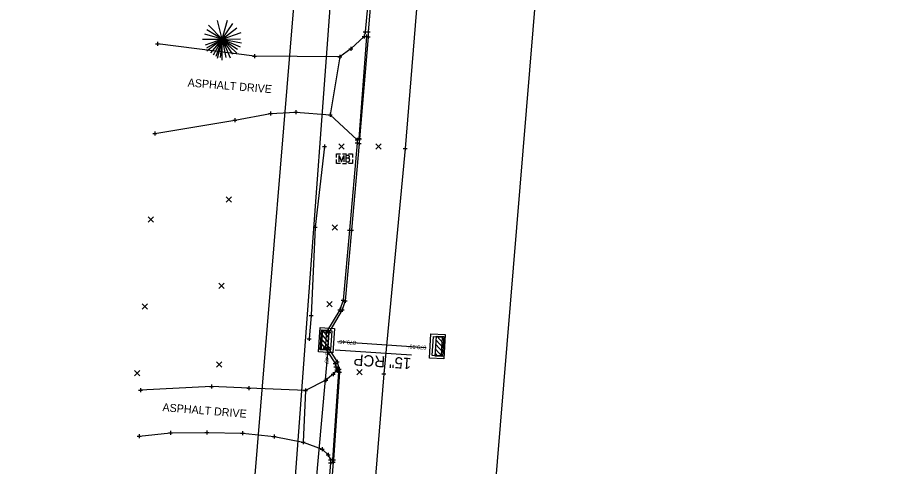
# Model space of a CAD drawing. Extents: x 1380550 to 1381945, y 468927 to 470496.
# Drawn here: x 1381450.4 to 1381668.9, y 469266.4 to 469378.6 of the extents above; entities that cross this region are included whole.
import ezdxf

# ---------------------------------------------------------------- set-up
doc = ezdxf.new("R2010")
doc.units = 0
for name, color, linetype in [('DR_X_Cells', 7, 'Continuous'), ('DR_X_Ditch', 7, 'Continuous'), ('DR_X_Storm_Sewer', 7, 'Continuous'), ('DR_X_Text', 7, 'Continuous'), ('GK_Drainage_Nodes', 7, 'Continuous'), ('PV_X_COP', 7, 'Continuous'), ('PV_X_Curb', 7, 'Continuous'), ('PV_X_Driveway', 7, 'Continuous'), ('PV_X_EOP', 7, 'Continuous'), ('RD_X_Cells', 7, 'Continuous'), ('RD_X_Text', 7, 'Continuous'), ('RW_X_Esmt_General', 7, 'Continuous'), ('SC_Scratch1', 7, 'Continuous'), ('SV_X_Random_Point', 7, 'Continuous'), ('SV_X_Shot_Marker', 7, 'Continuous'), ('UT_X_Electric', 7, 'Continuous'), ('UT_X_Telecom', 7, 'Continuous'), ('VG_X_Cells', 7, 'Continuous')]:
    doc.layers.add(name, color=color, linetype=linetype)

msp = doc.modelspace()

# ---------------------------------------------------------------- linework, layer by layer
at = {"layer": 'DR_X_Cells'}
for p, q in [((1381526.46, 469300.57), (1381528.09, 469298.69)), ((1381527.59, 469300.49), (1381528.17, 469299.82)), ((1381526.23, 469298.39), (1381527.93, 469296.44)), ((1381526.31, 469299.52), (1381528.01, 469297.56)), ((1381556.79, 469296.04), (1381555.06, 469297.97)), ((1381556.85, 469297.17), (1381555.25, 469298.95)), ((1381556.91, 469298.3), (1381556.39, 469298.89)), ((1381526.07, 469296.14), (1381526.58, 469295.54)), ((1381526.15, 469297.26), (1381527.71, 469295.46)), ((1381556.59, 469293.87), (1381554.93, 469295.72)), ((1381556.72, 469294.92), (1381554.99, 469296.84)), ((1381555.46, 469293.93), (1381554.87, 469294.59))]:
    msp.add_line(p, q, dxfattribs=at)
for points in [[(1381529.67, 469300.88), (1381529.23, 469294.81), (1381525.66, 469295.07), (1381526.09, 469301.14)], [(1381528.22, 469300.44), (1381527.86, 469295.45), (1381526.03, 469295.58), (1381526.39, 469300.57)], [(1381528.96, 469300.26), (1381528.62, 469295.52), (1381526.37, 469295.69), (1381526.71, 469300.42)], [(1381553.39, 469293.5), (1381553.73, 469299.58), (1381557.3, 469299.38), (1381556.97, 469293.3)], [(1381554.09, 469294.13), (1381554.36, 469298.87), (1381556.6, 469298.75), (1381556.34, 469294.01)], [(1381554.84, 469293.96), (1381555.11, 469298.96), (1381556.94, 469298.85), (1381556.67, 469293.86)]]:
    msp.add_lwpolyline(points, close=True, dxfattribs=at)
at = {"layer": 'DR_X_Ditch'}
msp.add_lwpolyline([(1381527.14, 469346.36), (1381524.79, 469326.2), (1381523.85, 469304.1), (1381523.31, 469298.29)], dxfattribs=at)
at = {"layer": 'DR_X_Storm_Sewer'}
for p, q in [((1381528.04, 469296.45), (1381500.71, 468992.41)), ((1381552.6, 469296.08), (1381530.41, 469297.57))]:
    msp.add_line(p, q, dxfattribs=at)
at = {"layer": 'DR_X_Text'}
msp.add_line((1381529.85, 469295.58), (1381548.9, 469294.3), dxfattribs=at)
at = {"layer": 'GK_Drainage_Nodes'}
for p, q in [((1381527.83, 469300.34), (1381527.83, 469300.34)), ((1381525.88, 469298.1), (1381525.88, 469298.1)), ((1381526.54, 469298.05), (1381526.54, 469298.05)), ((1381527.66, 469297.97), (1381527.66, 469297.97)), ((1381528.04, 469297.95), (1381528.04, 469297.95)), ((1381528.04, 469297.95), (1381528.04, 469297.95)), ((1381528.79, 469297.89), (1381528.79, 469297.89)), ((1381529.45, 469297.85), (1381529.45, 469297.85)), ((1381555.48, 469298.81), (1381555.48, 469298.81)), ((1381527.49, 469295.6), (1381527.49, 469295.6)), ((1381553.56, 469296.54), (1381553.56, 469296.54)), ((1381554.22, 469296.5), (1381554.22, 469296.5)), ((1381554.97, 469296.46), (1381554.97, 469296.46)), ((1381554.97, 469296.46), (1381554.97, 469296.46)), ((1381555.35, 469296.44), (1381555.35, 469296.44)), ((1381556.47, 469296.38), (1381556.47, 469296.38)), ((1381557.14, 469296.34), (1381557.14, 469296.34)), ((1381555.22, 469294.07), (1381555.22, 469294.07))]:
    msp.add_line(p, q, dxfattribs=at)
at = {"layer": 'PV_X_COP'}
msp.add_lwpolyline([(1381585.99, 469815.58), (1381581.29, 469760.78), (1381580.3, 469747.86), (1381578.72, 469729.45), (1381576.78, 469708.95), (1381575.29, 469689.79), (1381572.76, 469657.56), (1381569.36, 469615.7), (1381565.36, 469567.23), (1381561.16, 469537.52), (1381558.94, 469486.81), (1381555.39, 469442.03), (1381550.97, 469391.02), (1381547.28, 469345.9), (1381541.95, 469289.55), (1381537.19, 469231.27), (1381533.05, 469168.09), (1381530.32, 469133.74), (1381523.97, 469065.08), (1381520.12, 469021.37), (1381518.18, 469001.31)], dxfattribs=at)
at = {"layer": 'PV_X_Curb'}
for points in [[(1381538.96, 469393.9), (1381538.97, 469392.95), (1381537.34, 469375.04), (1381537.07, 469373.85)], [(1381535.34, 469347.99), (1381535.28, 469347.29), (1381533.36, 469325.49), (1381531.78, 469307.95), (1381530.98, 469305.57), (1381527.65, 469300.02), (1381527.35, 469296.02), (1381529.77, 469292.16), (1381529.97, 469291.26), (1381530.24, 469290.52)], [(1381528.62, 469268.06), (1381528.68, 469267.34), (1381525.83, 469232.26), (1381523.03, 469197.27), (1381522.81, 469196)]]:
    msp.add_lwpolyline(points, dxfattribs=at)
at = {"layer": 'PV_X_Driveway'}
for points in [[(1381537.07, 469373.85), (1381533.72, 469370.74), (1381530.94, 469368.81), (1381528.58, 469354.27), (1381535.34, 469347.99)], [(1381537.07, 469373.85), (1381537.66, 469373.84), (1381535.7, 469348.38), (1381535.34, 469347.99)], [(1381530.94, 469368.81), (1381509.64, 469368.9), (1381485.43, 469371.98)], [(1381484.73, 469349.64), (1381504.73, 469352.92), (1381513.61, 469354.59), (1381519.99, 469354.96), (1381528.58, 469354.27)], [(1381530.24, 469290.52), (1381529.29, 469289.43), (1381527.48, 469288), (1381522.43, 469285.41), (1381521.8, 469272.45), (1381526.53, 469270.72), (1381528.04, 469269.3), (1381528.62, 469268.06)], [(1381530.24, 469290.52), (1381530.57, 469290.63), (1381530.67, 469290.02), (1381529.16, 469268.09), (1381528.62, 469268.06)], [(1381522.43, 469285.41), (1381508.26, 469285.98), (1381498.91, 469286.38), (1381481.14, 469285.44)], [(1381480.8, 469273.97), (1381488.65, 469274.82), (1381497.76, 469274.89), (1381506.68, 469274.7), (1381514.52, 469273.9), (1381521.8, 469272.45)]]:
    msp.add_lwpolyline(points, dxfattribs=at)
at = {"layer": 'PV_X_EOP'}
msp.add_line((1381533.72, 469370.74), (1381533.72, 469370.74), dxfattribs=at)
msp.add_lwpolyline([(1381539.58, 469392.93), (1381538.09, 469374.98), (1381538.03, 469373.76), (1381535.92, 469348.28), (1381535.79, 469347.09), (1381533.91, 469325.42), (1381532.32, 469307.8), (1381531.56, 469305.55), (1381528.19, 469299.9), (1381527.99, 469296.13), (1381530.34, 469292.53), (1381530.8, 469290.75), (1381530.92, 469290), (1381529.4, 469268.09), (1381529.3, 469267.44), (1381526.47, 469232.31), (1381523.61, 469197.35), (1381523.61, 469196.13), (1381521.19, 469168.77), (1381520.16, 469156.66)], dxfattribs=at)
at = {"layer": 'RD_X_Cells'}
for p, q in [((1381531.63, 469344.56), (1381532.63, 469344.56)), ((1381531.63, 469342.12), (1381532.63, 469342.12)), ((1381532.14, 469343.34), (1381532.14, 469343.34))]:
    msp.add_line(p, q, dxfattribs=at)
for points in [[(1381530.14, 469343.59), (1381530.14, 469344.56), (1381531.11, 469344.56)], [(1381530.85, 469342.54), (1381530.85, 469344.14), (1381531.43, 469342.54), (1381531.98, 469344.14), (1381531.98, 469342.54)], [(1381533.16, 469343.41), (1381533.23, 469343.47), (1381533.26, 469343.51), (1381533.29, 469343.55), (1381533.3, 469343.57), (1381533.33, 469343.62), (1381533.34, 469343.66), (1381533.37, 469343.75), (1381533.37, 469343.79), (1381533.37, 469343.84), (1381533.35, 469343.91), (1381533.33, 469343.98), (1381533.29, 469344.03), (1381533.23, 469344.08), (1381533.18, 469344.1), (1381533.15, 469344.11), (1381533.09, 469344.14), (1381532.47, 469344.14), (1381532.47, 469342.54), (1381533.16, 469342.54), (1381533.25, 469342.59), (1381533.33, 469342.65), (1381533.39, 469342.75), (1381533.43, 469342.87), (1381533.44, 469342.98), (1381533.44, 469343.06), (1381533.42, 469343.13), (1381533.37, 469343.25), (1381533.3, 469343.32), (1381533.16, 469343.41), (1381532.47, 469343.41)], [(1381533.15, 469344.56), (1381534.14, 469344.56), (1381534.14, 469343.59)], [(1381531.11, 469342.12), (1381530.14, 469342.12), (1381530.14, 469343.09)], [(1381534.14, 469343.09), (1381534.14, 469342.12), (1381533.15, 469342.12)]]:
    msp.add_lwpolyline(points, dxfattribs=at)
at = {"layer": 'RW_X_Esmt_General'}
for points in [[(1381490.4, 469029.46), (1381590.2, 470237.18), (1380558.69, 470277.03)], [(1381783.19, 470213.89), (1381648.78, 470217.49), (1381563.79, 469189.03)]]:
    msp.add_lwpolyline(points, dxfattribs=at)
at = {"layer": 'SV_X_Random_Point'}
for p, q in [((1381530.69, 469345.66), (1381532.03, 469347)), ((1381530.69, 469347), (1381532.03, 469345.66)), ((1381539.96, 469345.66), (1381541.3, 469346.99)), ((1381539.96, 469346.99), (1381541.3, 469345.66)), ((1381502.57, 469332.47), (1381503.9, 469333.8)), ((1381502.57, 469333.8), (1381503.9, 469332.47)), ((1381483.09, 469327.43), (1381484.43, 469328.77)), ((1381483.09, 469328.77), (1381484.43, 469327.43)), ((1381529.05, 469325.46), (1381530.39, 469326.8)), ((1381529.05, 469326.8), (1381530.39, 469325.46)), ((1381500.73, 469310.9), (1381502.06, 469312.23)), ((1381500.73, 469312.23), (1381502.06, 469310.9)), ((1381481.56, 469305.72), (1381482.89, 469307.06)), ((1381481.56, 469307.06), (1381482.89, 469305.72)), ((1381527.74, 469306.31), (1381529.07, 469307.65)), ((1381527.74, 469307.65), (1381529.07, 469306.31)), ((1381500.16, 469291.24), (1381501.49, 469292.58)), ((1381500.16, 469292.58), (1381501.49, 469291.24)), ((1381479.67, 469289.03), (1381481, 469290.37)), ((1381479.67, 469290.37), (1381481, 469289.03)), ((1381535.2, 469289.33), (1381536.53, 469290.66)), ((1381535.2, 469290.66), (1381536.53, 469289.33))]:
    msp.add_line(p, q, dxfattribs=at)
at = {"layer": 'SV_X_Shot_Marker'}
for p, q in [((1381536.84, 469375.04), (1381537.84, 469375.04)), ((1381537.07, 469374.35), (1381537.07, 469373.35)), ((1381537.07, 469374.35), (1381537.07, 469373.35)), ((1381537.07, 469374.35), (1381537.07, 469373.35)), ((1381537.34, 469375.54), (1381537.34, 469374.54)), ((1381537.34, 469375.04), (1381537.34, 469375.04)), ((1381537.59, 469374.98), (1381538.59, 469374.98)), ((1381537.66, 469374.34), (1381537.66, 469373.34)), ((1381538.03, 469374.26), (1381538.03, 469373.26)), ((1381538.09, 469375.48), (1381538.09, 469374.48)), ((1381538.09, 469374.98), (1381538.09, 469374.98)), ((1381485.43, 469372.48), (1381485.43, 469371.48)), ((1381536.57, 469373.85), (1381537.57, 469373.85)), ((1381536.57, 469373.85), (1381537.57, 469373.85)), ((1381536.57, 469373.85), (1381537.57, 469373.85)), ((1381537.07, 469373.85), (1381537.07, 469373.85)), ((1381537.07, 469373.85), (1381537.07, 469373.85)), ((1381537.07, 469373.85), (1381537.07, 469373.85)), ((1381537.16, 469373.84), (1381538.16, 469373.84)), ((1381537.53, 469373.76), (1381538.53, 469373.76)), ((1381537.66, 469373.84), (1381537.66, 469373.84)), ((1381538.03, 469373.76), (1381538.03, 469373.76)), ((1381484.93, 469371.98), (1381485.93, 469371.98)), ((1381485.43, 469371.98), (1381485.43, 469371.98)), ((1381533.22, 469370.74), (1381534.22, 469370.74)), ((1381533.22, 469370.74), (1381534.22, 469370.74)), ((1381533.72, 469371.24), (1381533.72, 469370.24)), ((1381533.72, 469371.24), (1381533.72, 469370.24)), ((1381533.72, 469370.74), (1381533.72, 469370.74)), ((1381533.72, 469370.74), (1381533.72, 469370.74)), ((1381509.14, 469368.9), (1381510.14, 469368.9)), ((1381509.64, 469369.4), (1381509.64, 469368.4)), ((1381509.64, 469368.9), (1381509.64, 469368.9)), ((1381530.44, 469368.81), (1381531.44, 469368.81)), ((1381530.44, 469368.81), (1381531.44, 469368.81)), ((1381530.94, 469369.31), (1381530.94, 469368.31)), ((1381530.94, 469369.31), (1381530.94, 469368.31)), ((1381530.94, 469368.81), (1381530.94, 469368.81)), ((1381530.94, 469368.81), (1381530.94, 469368.81)), ((1381513.11, 469354.59), (1381514.11, 469354.59)), ((1381513.61, 469355.09), (1381513.61, 469354.09)), ((1381513.61, 469354.59), (1381513.61, 469354.59)), ((1381519.49, 469354.96), (1381520.49, 469354.96)), ((1381519.99, 469355.46), (1381519.99, 469354.46)), ((1381519.99, 469354.96), (1381519.99, 469354.96)), ((1381528.58, 469354.77), (1381528.58, 469353.77)), ((1381528.58, 469354.77), (1381528.58, 469353.77)), ((1381504.23, 469352.92), (1381505.23, 469352.92)), ((1381504.73, 469353.42), (1381504.73, 469352.42)), ((1381504.73, 469352.92), (1381504.73, 469352.92)), ((1381528.08, 469354.27), (1381529.08, 469354.27)), ((1381528.08, 469354.27), (1381529.08, 469354.27)), ((1381528.58, 469354.27), (1381528.58, 469354.27)), ((1381528.58, 469354.27), (1381528.58, 469354.27)), ((1381484.23, 469349.64), (1381485.23, 469349.64)), ((1381484.73, 469350.14), (1381484.73, 469349.14)), ((1381484.73, 469349.64), (1381484.73, 469349.64)), ((1381535.2, 469348.38), (1381536.2, 469348.38)), ((1381535.34, 469348.49), (1381535.34, 469347.49)), ((1381535.34, 469348.49), (1381535.34, 469347.49)), ((1381535.34, 469348.49), (1381535.34, 469347.49)), ((1381535.42, 469348.28), (1381536.42, 469348.28)), ((1381535.7, 469348.88), (1381535.7, 469347.88)), ((1381535.7, 469348.38), (1381535.7, 469348.38)), ((1381535.92, 469348.78), (1381535.92, 469347.78)), ((1381535.92, 469348.28), (1381535.92, 469348.28)), ((1381526.64, 469346.36), (1381527.64, 469346.36)), ((1381527.14, 469346.86), (1381527.14, 469345.86)), ((1381527.14, 469346.36), (1381527.14, 469346.36)), ((1381534.78, 469347.29), (1381535.78, 469347.29)), ((1381534.84, 469347.99), (1381535.84, 469347.99)), ((1381534.84, 469347.99), (1381535.84, 469347.99)), ((1381534.84, 469347.99), (1381535.84, 469347.99)), ((1381535.28, 469347.79), (1381535.28, 469346.79)), ((1381535.28, 469347.29), (1381535.28, 469347.29)), ((1381535.29, 469347.09), (1381536.29, 469347.09)), ((1381535.34, 469347.99), (1381535.34, 469347.99)), ((1381535.34, 469347.99), (1381535.34, 469347.99)), ((1381535.34, 469347.99), (1381535.34, 469347.99)), ((1381535.79, 469347.59), (1381535.79, 469346.59)), ((1381535.79, 469347.09), (1381535.79, 469347.09)), ((1381546.78, 469345.9), (1381547.78, 469345.9)), ((1381547.28, 469346.4), (1381547.28, 469345.4)), ((1381547.28, 469345.9), (1381547.28, 469345.9)), ((1381524.29, 469326.2), (1381525.29, 469326.2)), ((1381524.79, 469326.7), (1381524.79, 469325.7)), ((1381524.79, 469326.2), (1381524.79, 469326.2)), ((1381532.86, 469325.49), (1381533.86, 469325.49)), ((1381533.36, 469325.99), (1381533.36, 469324.99)), ((1381533.36, 469325.49), (1381533.36, 469325.49)), ((1381533.41, 469325.42), (1381534.41, 469325.42)), ((1381533.91, 469325.92), (1381533.91, 469324.92)), ((1381533.91, 469325.42), (1381533.91, 469325.42)), ((1381531.28, 469307.95), (1381532.28, 469307.95)), ((1381531.78, 469308.45), (1381531.78, 469307.45)), ((1381531.78, 469307.95), (1381531.78, 469307.95)), ((1381531.82, 469307.8), (1381532.82, 469307.8)), ((1381532.32, 469308.3), (1381532.32, 469307.3)), ((1381532.32, 469307.8), (1381532.32, 469307.8)), ((1381523.85, 469304.6), (1381523.85, 469303.6)), ((1381530.48, 469305.57), (1381531.48, 469305.57)), ((1381530.98, 469306.07), (1381530.98, 469305.07)), ((1381530.98, 469305.57), (1381530.98, 469305.57)), ((1381531.06, 469305.55), (1381532.06, 469305.55)), ((1381531.56, 469306.05), (1381531.56, 469305.05)), ((1381531.56, 469305.55), (1381531.56, 469305.55)), ((1381523.35, 469304.1), (1381524.35, 469304.1)), ((1381523.85, 469304.1), (1381523.85, 469304.1)), ((1381527.15, 469300.02), (1381528.15, 469300.02)), ((1381527.65, 469300.52), (1381527.65, 469299.52)), ((1381527.65, 469300.02), (1381527.65, 469300.02)), ((1381528.19, 469300.4), (1381528.19, 469299.4)), ((1381522.81, 469298.29), (1381523.81, 469298.29)), ((1381523.31, 469298.79), (1381523.31, 469297.79)), ((1381523.31, 469298.29), (1381523.31, 469298.29)), ((1381527.69, 469299.9), (1381528.69, 469299.9)), ((1381528.19, 469299.9), (1381528.19, 469299.9)), ((1381526.85, 469296.02), (1381527.85, 469296.02)), ((1381527.35, 469296.52), (1381527.35, 469295.52)), ((1381527.35, 469296.02), (1381527.35, 469296.02)), ((1381527.49, 469296.13), (1381528.49, 469296.13)), ((1381527.99, 469296.63), (1381527.99, 469295.63)), ((1381527.99, 469296.13), (1381527.99, 469296.13)), ((1381529.27, 469292.16), (1381530.27, 469292.16)), ((1381529.47, 469291.26), (1381530.47, 469291.26)), ((1381529.77, 469292.66), (1381529.77, 469291.66)), ((1381529.77, 469292.16), (1381529.77, 469292.16)), ((1381529.84, 469292.53), (1381530.84, 469292.53)), ((1381529.97, 469291.76), (1381529.97, 469290.76)), ((1381529.97, 469291.26), (1381529.97, 469291.26)), ((1381530.34, 469293.03), (1381530.34, 469292.03)), ((1381530.34, 469292.53), (1381530.34, 469292.53)), ((1381530.8, 469291.25), (1381530.8, 469290.25)), ((1381528.79, 469289.43), (1381529.79, 469289.43)), ((1381529.29, 469289.93), (1381529.29, 469288.93)), ((1381529.29, 469289.43), (1381529.29, 469289.43)), ((1381529.74, 469290.52), (1381530.74, 469290.52)), ((1381529.74, 469290.52), (1381530.74, 469290.52)), ((1381529.74, 469290.52), (1381530.74, 469290.52)), ((1381530.07, 469290.63), (1381531.07, 469290.63)), ((1381530.17, 469290.02), (1381531.17, 469290.02)), ((1381530.24, 469291.02), (1381530.24, 469290.02)), ((1381530.24, 469291.02), (1381530.24, 469290.02)), ((1381530.24, 469291.02), (1381530.24, 469290.02)), ((1381530.24, 469290.52), (1381530.24, 469290.52)), ((1381530.24, 469290.52), (1381530.24, 469290.52)), ((1381530.24, 469290.52), (1381530.24, 469290.52)), ((1381530.3, 469290.75), (1381531.3, 469290.75)), ((1381530.42, 469290), (1381531.42, 469290)), ((1381530.57, 469291.13), (1381530.57, 469290.13)), ((1381530.57, 469290.63), (1381530.57, 469290.63)), ((1381530.67, 469290.52), (1381530.67, 469289.52)), ((1381530.67, 469290.02), (1381530.67, 469290.02)), ((1381530.8, 469290.75), (1381530.8, 469290.75)), ((1381530.92, 469290.5), (1381530.92, 469289.5)), ((1381530.92, 469290), (1381530.92, 469290)), ((1381541.45, 469289.55), (1381542.45, 469289.55)), ((1381541.95, 469290.05), (1381541.95, 469289.05)), ((1381541.95, 469289.55), (1381541.95, 469289.55)), ((1381498.91, 469286.88), (1381498.91, 469285.88)), ((1381526.98, 469288), (1381527.98, 469288)), ((1381527.48, 469288.5), (1381527.48, 469287.5)), ((1381527.48, 469288), (1381527.48, 469288)), ((1381480.64, 469285.44), (1381481.64, 469285.44)), ((1381481.14, 469285.94), (1381481.14, 469284.94)), ((1381481.14, 469285.44), (1381481.14, 469285.44)), ((1381498.41, 469286.38), (1381499.41, 469286.38)), ((1381498.91, 469286.38), (1381498.91, 469286.38)), ((1381507.76, 469285.98), (1381508.76, 469285.98)), ((1381508.26, 469286.48), (1381508.26, 469285.48)), ((1381508.26, 469285.98), (1381508.26, 469285.98)), ((1381521.93, 469285.41), (1381522.93, 469285.41)), ((1381521.93, 469285.41), (1381522.93, 469285.41)), ((1381522.43, 469285.91), (1381522.43, 469284.91)), ((1381522.43, 469285.91), (1381522.43, 469284.91)), ((1381522.43, 469285.41), (1381522.43, 469285.41)), ((1381522.43, 469285.41), (1381522.43, 469285.41)), ((1381480.3, 469273.97), (1381481.3, 469273.97)), ((1381480.8, 469274.47), (1381480.8, 469273.47)), ((1381480.8, 469273.97), (1381480.8, 469273.97)), ((1381488.15, 469274.82), (1381489.15, 469274.82)), ((1381488.65, 469275.32), (1381488.65, 469274.32)), ((1381488.65, 469274.82), (1381488.65, 469274.82)), ((1381497.26, 469274.89), (1381498.26, 469274.89)), ((1381497.76, 469275.39), (1381497.76, 469274.39)), ((1381497.76, 469274.89), (1381497.76, 469274.89)), ((1381506.18, 469274.7), (1381507.18, 469274.7)), ((1381506.68, 469275.2), (1381506.68, 469274.2)), ((1381506.68, 469274.7), (1381506.68, 469274.7)), ((1381514.02, 469273.9), (1381515.02, 469273.9)), ((1381514.52, 469274.4), (1381514.52, 469273.4)), ((1381514.52, 469273.9), (1381514.52, 469273.9)), ((1381521.3, 469272.45), (1381522.3, 469272.45)), ((1381521.3, 469272.45), (1381522.3, 469272.45)), ((1381521.8, 469272.95), (1381521.8, 469271.95)), ((1381521.8, 469272.95), (1381521.8, 469271.95)), ((1381521.8, 469272.45), (1381521.8, 469272.45)), ((1381521.8, 469272.45), (1381521.8, 469272.45)), ((1381526.03, 469270.72), (1381527.03, 469270.72)), ((1381526.53, 469271.22), (1381526.53, 469270.22)), ((1381526.53, 469270.72), (1381526.53, 469270.72)), ((1381528.04, 469269.8), (1381528.04, 469268.8)), ((1381527.54, 469269.3), (1381528.54, 469269.3)), ((1381528.04, 469269.3), (1381528.04, 469269.3)), ((1381528.12, 469268.06), (1381529.12, 469268.06)), ((1381528.12, 469268.06), (1381529.12, 469268.06)), ((1381528.12, 469268.06), (1381529.12, 469268.06)), ((1381528.12, 469268.06), (1381529.12, 469268.06)), ((1381528.18, 469267.34), (1381529.18, 469267.34)), ((1381528.62, 469268.56), (1381528.62, 469267.56)), ((1381528.62, 469268.56), (1381528.62, 469267.56)), ((1381528.62, 469268.56), (1381528.62, 469267.56)), ((1381528.62, 469268.56), (1381528.62, 469267.56)), ((1381528.62, 469268.06), (1381528.62, 469268.06)), ((1381528.62, 469268.06), (1381528.62, 469268.06)), ((1381528.62, 469268.06), (1381528.62, 469268.06)), ((1381528.62, 469268.06), (1381528.62, 469268.06)), ((1381528.66, 469268.09), (1381529.66, 469268.09)), ((1381528.68, 469267.84), (1381528.68, 469266.84)), ((1381528.68, 469267.34), (1381528.68, 469267.34)), ((1381528.8, 469267.44), (1381529.8, 469267.44)), ((1381528.9, 469268.09), (1381529.9, 469268.09)), ((1381529.16, 469268.59), (1381529.16, 469267.59)), ((1381529.16, 469268.09), (1381529.16, 469268.09)), ((1381529.3, 469267.94), (1381529.3, 469266.94)), ((1381529.3, 469267.44), (1381529.3, 469267.44)), ((1381529.4, 469268.59), (1381529.4, 469267.59)), ((1381529.4, 469268.09), (1381529.4, 469268.09))]:
    msp.add_line(p, q, dxfattribs=at)
at = {"layer": 'UT_X_Electric'}
msp.add_lwpolyline([(1381665.56, 470247.4), (1381595.79, 470220.83), (1381581.26, 470018.2), (1381571.97, 469887.64), (1381559.77, 469757.41), (1381543.86, 469565.78), (1381529.17, 469390.12), (1381515.28, 469203.1), (1381540.8, 469054.26)], dxfattribs=at)
at = {"layer": 'UT_X_Telecom'}
msp.add_lwpolyline([(1381665.56, 470247.4), (1381595.35, 470217.51), (1381581.26, 470018.2), (1381571.97, 469887.64), (1381559.77, 469757.41), (1381543.86, 469565.78), (1381529.17, 469390.12), (1381515.28, 469203.1), (1381540.8, 469054.26)], dxfattribs=at)
at = {"layer": 'VG_X_Cells'}
for p, q in [((1381501.6, 469373.21), (1381498.11, 469376.7)), ((1381501.6, 469373.21), (1381500.37, 469377.83)), ((1381501.6, 469373.21), (1381502.86, 469377.91)), ((1381501.6, 469373.21), (1381504.26, 469377.1)), ((1381501.6, 469373.21), (1381497.19, 469374.4)), ((1381501.6, 469373.21), (1381497.7, 469375.51)), ((1381501.6, 469373.21), (1381505.26, 469376.02)), ((1381501.6, 469373.21), (1381506.34, 469374.82)), ((1381496.67, 469373.21), (1381501.6, 469373.21)), ((1381501.6, 469373.21), (1381497.31, 469371.65)), ((1381501.6, 469373.21), (1381497.62, 469370.93)), ((1381501.6, 469373.21), (1381497.7, 469370.22)), ((1381501.6, 469373.21), (1381498.66, 469369.75)), ((1381501.6, 469373.21), (1381499.28, 469369.2)), ((1381501.6, 469373.21), (1381499.94, 469368.87)), ((1381501.6, 469373.21), (1381500.34, 469368.36)), ((1381501.6, 469373.21), (1381501.06, 469368.62)), ((1381501.6, 469373.21), (1381506.11, 469373.3)), ((1381501.6, 469367.97), (1381501.6, 469373.21)), ((1381501.6, 469373.21), (1381502.52, 469368.58)), ((1381501.6, 469373.21), (1381503.54, 469368.54)), ((1381501.6, 469373.21), (1381504.14, 469369.42)), ((1381501.6, 469373.21), (1381505.19, 469369.69)), ((1381501.6, 469373.21), (1381505.42, 469370.66)), ((1381501.6, 469373.21), (1381506.07, 469371.27)), ((1381501.6, 469373.21), (1381506.43, 469372.25))]:
    msp.add_line(p, q, dxfattribs=at)

# ---------------------------------------------------------------- texts
at = {"layer": 'DR_X_Text'}
msp.add_text('15" RCP', height=2.8, rotation=176.166, dxfattribs=at).set_placement((1381548.9, 469293.48))
at = {"layer": 'RD_X_Text'}
for p in [(1381492.88, 469361.36), (1381486.58, 469280.23)]:
    msp.add_text('ASPHALT DRIVE', height=2, rotation=355.4428, dxfattribs=at).set_placement(p)
at = {"layer": 'SC_Scratch1'}
for s, rotation, p in [("879.45'", 176.166, (1381535.07, 469297.76)), ("879.45'", 264.8634, (1381527.54, 469296.49)), ("879.99'", 176.166, (1381552.63, 469296.58))]:
    msp.add_text(s, height=1, rotation=rotation, dxfattribs=at).set_placement(p)

doc.saveas('drawing.dxf')
